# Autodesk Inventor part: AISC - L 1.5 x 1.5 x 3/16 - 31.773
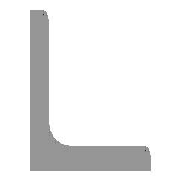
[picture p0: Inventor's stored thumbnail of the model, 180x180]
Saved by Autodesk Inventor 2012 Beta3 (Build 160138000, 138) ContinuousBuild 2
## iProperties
_CCFamilyMember: 5
_CCFamilyDisplayName: ANSI L (Equal angles) - Angle Steel
_FrameMemberDoc: Frame Member File
_Version: 15.0.0
_GetPNFromCC: 1
Created: 2010-11
Part Number: AISC - L 1.5 x 1.5 x 3/16 - 31.773
Material: Steel, Mild
Description: Angle Steel
Document SubType Name: Modeling
Standard: ANSI
Designer: Beta-8540w
Standards Organization: ANSI
Language: en-US
Size Designation: L 1.5 x 1.5 x 3/16
Categories: <MemberInstance><Categories><Category DisplayName="Structural Shapes" InternalName="089c4875-fa83-4c05-b084-43b9cc11f5ed" Mnemonic="GRDR"><CategoryParameter Dis
Stock Number: L 1.5 x 1.5 x 3/16
Density: 7.86 g/cm^3
IsCustomPart: 1
G_L: 31.773 in
G_W: 1.500 in
G_H: 1.500 in
+D492D07F-02B9-496C-B776-82EB711B3C50+CUTDETAIL1: Cut
Author: Beta-8540w
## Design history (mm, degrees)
node "Start plane"
node "End plane"
sketch "Sketch"
  geometry: L1 (38.1, 0)-(0, 0); L2 (0, 0)-(0, 38.1); L3 (0, 38.1)-(2.476, 38.1); L4 (4.762, 35.814)-(4.762, 9.589); L5 (9.588, 4.763)-(35.814, 4.763); L6 (38.1, 2.477)-(38.1, 0); L7 (0, -11.041)-(0, 31.538); L8 (-11.041, 0)-(31.538, 0); L9 (0, 48.496)-(0, -20.964) reference; L10 (-20.964, 0)-(48.496, 0) reference; A1 r 4.826 centre (9.588, 9.589) between (4.762, 9.589) and (9.588, 4.763); A2 r 2.286 centre (2.476, 35.814) between (4.762, 35.814) and (2.476, 38.1); A3 r 2.286 centre (35.814, 2.477) between (38.1, 2.477) and (35.814, 4.763); 3 further points
  constraints: 16 end point, 6 point on circle, 6 point on line, 6 tangent, 4 parallel, 3 centre point, 2 collinear, 1 equal radius, 1 horizontal, 1 perpendicular
  dimensions: "d0" = 38.1 distance between parallel lines of L6 L2 (= G_H); "d1" = 38.1 distance between parallel lines of L3 L1 (= G_H); "d2" = 4.7625 distance between parallel lines of L2 L4 (= G_T); "d3" = 4.7625 distance between parallel lines of L1 L5 (= G_T); "d10" = 0 distance between parallel lines of L7 L2 (computed from ex); "d11" = 0 distance between parallel lines of L8 L1 (computed from d10); "d14" = 4.826 radius of A1 (= G_IR); "d15" = 2.286 radius of A2 (= G_ER)
extrude "Body" new body sketch "Sketch" stored distance "d4" = 807.0404 (= G_L); taper "d5" = 0 deg
node "Driven Length"
  sketch "Sketch3"
    geometry: L1 (0, 0)-(10, 0) reference
    constraints: 2 end point, 1 horizontal
  workplane "Work Plane3"
  sketch "Sketch4"
    geometry: L1 (-2, 0)-(12, 0) reference; L2 (-2, 807.04)-(12, 807.04) reference
    dimensions: "d17" = 807.0404 distance between parallel lines of L1 L2 (derived)
workplane "Work Plane4"
split "Split1"
body "Solid1"
other parameters: "G_H" = 38.1 [user parameter; used in 2 equation terms], "G_T" = 4.7625 [user parameter; used in 2 equation terms], "G_ER" = 2.286 [user parameter; used in 1 equation term], "G_IR" = 4.826 [user parameter; used in 1 equation term], "G_L" = 807.0404 (= d17) [user parameter; used in 1 equation term], "ex" = 0 [user parameter; used in 1 equation term], "G_OFFSET_START" = 0 [user parameter; used in 1 equation term], "G_OFFSET_END" = -29.72503 [user parameter; used in 1 equation term], "d12" = 0 (computed from G_OFFSET_START), "d13" = 807.0404 (= G_OFFSET_END + B_L), "B_L" = 836.76542 [user parameter; used in 1 equation term], "d16" = 90 deg, "MAS" = 0.26787 [user parameter]
